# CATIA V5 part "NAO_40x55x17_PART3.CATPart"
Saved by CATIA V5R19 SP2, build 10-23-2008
Part number: NAO_40x55x17_PART3
Bounding box of the stored display mesh (mm): x 1.6 to 15.4, y 22.551 to 24.949, z -1.199 to 1.199
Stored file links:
  G:\EU_thinkMotion\CFAO_2010\MMS_groupe2\MMS_groupe2\OK\nrosalie\nrosalie_cfao_support_d_arme_legere_final\NAO_40x55x17_PART3.CATPart
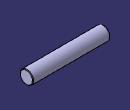
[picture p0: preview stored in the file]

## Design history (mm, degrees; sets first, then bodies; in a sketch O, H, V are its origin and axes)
Set1
  Point1: (0, 0, 0)
  Point2: (1, 0, 0)
  Point3: (0, 1, 0)
  Plane1: type 3Points, Element1 Point1, Element2 Point2, Element3 Point3
Body1 (main body)
  Sketch1 on Plane1, origin (0, 0, 0), H (1, 0, 0), V (0, 1, 0)
    point P1 (1.6, 23.75)
    point P2 (1.6, 24.9)
    line L1 (1.6, 23.75) -> (1.6, 24.9)
    arc A1 centre (1.7, 24.9) radius 0.1 from (1.7, 25) to (1.6, 24.9) ccw
    point P3 (1.7, 25)
    point P4 (15.3, 25)
    line L2 (1.7, 25) -> (15.3, 25)
    arc A2 centre (15.3, 24.9) radius 0.1 from (15.4, 24.9) to (15.3, 25) ccw
    point P5 (15.4, 24.9)
    point P6 (15.4, 23.75)
    line L3 (15.4, 24.9) -> (15.4, 23.75)
    point P7 (15.4, 23.75)
    point P8 (1.6, 23.75)
    line L4 (15.4, 23.75) -> (1.6, 23.75)
    point P9 (15.4, 23.75)
    point P10 (1.6, 23.75)
    axis line L5 (15.4, 23.75) -> (1.6, 23.75)
    point P11 (1.6, 23.75)
    point P12 (1.6, 24.9)
    point P13 (1.7, 25)
    point P14 (1.6, 24.9)
    point P15 (1.7, 25)
    point P16 (15.3, 25)
    point P17 (15.4, 24.9)
    point P18 (15.3, 25)
    point P19 (15.4, 24.9)
    point P20 (15.4, 23.75)
    point P21 (15.4, 23.75)
    point P22 (1.6, 23.75)
    coincidence: P11 P22, P12 P14, P13 P15, P16 P18, P17 P19, P20 P21
  Shaft1: profile Sketch1, axis Sketch1.L5, angle 360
